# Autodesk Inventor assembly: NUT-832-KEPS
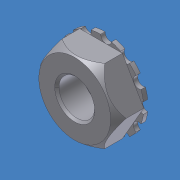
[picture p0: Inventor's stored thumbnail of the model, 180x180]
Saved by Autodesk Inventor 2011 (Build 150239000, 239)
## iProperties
Created: 2007-09
Part Number: NUT-832-KEPS
Document SubType Name: Assembly
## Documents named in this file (3)
- C:\Data Folder\VEX 2011\Inventor Datasets\Unit 6\Components\NUT-832-KEPS.iam
- C:\Data Folder\VEX 2011\Inventor Datasets\Unit 6\Components\8-32 KEPS NUT-1.ipt
- C:\Data Folder\VEX 2011\Inventor Datasets\Unit 6\Components\8-32 KEPS NUT-2.ipt
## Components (2 placed, 2 different names)
1. 8-32 KEPS NUT-1:1 — Insert:1
2. 8-32 KEPS NUT-2:1 — Insert:1
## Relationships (1: Insert 1)
- Insert:1: 8-32 KEPS NUT-1:1 ↔ 8-32 KEPS NUT-2:1
